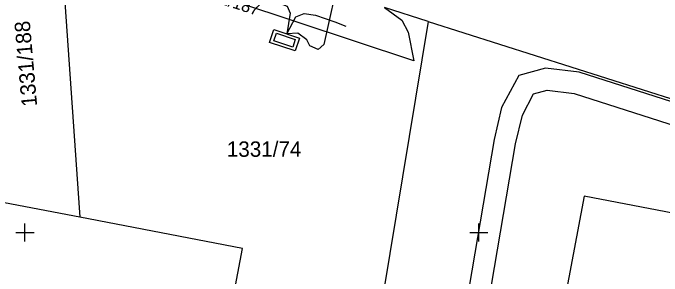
# Model space of a CAD drawing. Extents: x -601602 to -600882, y -1162594 to -1161950.
# Drawn here: x -601150.66 to -601114.91, y -1162127.4 to -1162112.9 of the extents above; entities that cross this region are included whole.
import ezdxf

# ---------------------------------------------------------------- set-up
doc = ezdxf.new("R2010")
doc.units = 0
for name, color, linetype in [('IS_EON_NN', 7, 'Continuous'), ('KN_Hranice parcel', 7, 'Continuous'), ('KN_Parcelní čísla', 7, 'Continuous'), ('KN_Věcná břemena k části', 7, 'Continuous'), ('X_SOUR_KRIZKY_SEVER', 7, 'Continuous')]:
    doc.layers.add(name, color=color, linetype=linetype)

# ---------------------------------------------------------------- blocks, each defined once
blk = doc.blocks.new('132_9')
at = {"layer": 'IS_EON_NN'}
for points in [[(-1.5, 1.5), (1.5, 1.5), (1.5, 0), (-1.5, 0)], [(-1.1, 1.2), (1.1, 1.2), (1.1, 0.3), (-1.1, 0.3)]]:
    blk.add_lwpolyline(points, close=True, dxfattribs=at)

msp = doc.modelspace()

# ---------------------------------------------------------------- linework, layer by layer
at = {"layer": 'IS_EON_NN'}
for points in [[(-601130.83, -1162102.5), (-601133.53, -1162114.65), (-601133.84, -1162114.91), (-601134.3, -1162114.72), (-601134.48, -1162114.39), (-601134.96, -1162114.02), (-601135.58, -1162114.05)], [(-601138.29, -1162111.45), (-601135.56, -1162112.52), (-601135.39, -1162112.91), (-601135.58, -1162114.05)], [(-601135.58, -1162114.05), (-601135.07, -1162113.12), (-601134.61, -1162112.94), (-601134, -1162113.02), (-601132.93, -1162113.4), (-601132.32, -1162113.64)]]:
    msp.add_lwpolyline(points, dxfattribs=at)
at = {"layer": 'KN_Hranice parcel'}
for p, q in [((-601148.03, -1162109.07), (-601146.98, -1162124.15)), ((-601127.79, -1162113.37), (-601130.19, -1162112.6)), ((-601127.79, -1162113.37), (-601132.96, -1162144.65)), ((-601127.79, -1162113.37), (-601109.09, -1162119.33)), ((-601146.98, -1162124.15), (-601153.26, -1162122.95))]:
    msp.add_line(p, q, dxfattribs=at)
for points in [[(-601130.19, -1162112.6), (-601129.24, -1162113.3), (-601128.89, -1162113.97), (-601128.58, -1162115.55), (-601148.03, -1162109.07)], [(-601091.03, -1162134.77), (-601093.93, -1162134.22), (-601092.77, -1162128.06), (-601119.19, -1162123), (-601124.02, -1162148.61), (-601098.1, -1162153.53), (-601099.02, -1162158.39)], [(-601145.82, -1162139.06), (-601137.26, -1162140.71), (-601135.56, -1162132.45), (-601139.12, -1162131.71), (-601138.01, -1162125.88), (-601146.98, -1162124.15)]]:
    msp.add_lwpolyline(points, dxfattribs=at)
at = {"layer": 'KN_Věcná břemena k části'}
msp.add_lwpolyline([(-601071.86, -1162133.64), (-601078.97, -1162129.14), (-601092.68, -1162124.75), (-601119.48, -1162116.16), (-601121.32, -1162115.94), (-601122.8, -1162116.34), (-601123.74, -1162118.12), (-601124.16, -1162119.88), (-601128.74, -1162146.87), (-601133.21, -1162146.17), (-601133.4, -1162147.34), (-601127.76, -1162148.23), (-601122.98, -1162120.12), (-601122.6, -1162118.54), (-601121.98, -1162117.36), (-601121.24, -1162117.16), (-601119.74, -1162117.34), (-601092.46, -1162126.08), (-601079.49, -1162130.24), (-601072.6, -1162134.6)], dxfattribs=at)
at = {"layer": 'X_SOUR_KRIZKY_SEVER'}
for p, q in [((-601150, -1162125.5), (-601150, -1162124.5)), ((-601125, -1162125.5), (-601125, -1162124.5)), ((-601150.5, -1162125), (-601149.5, -1162125)), ((-601125.5, -1162125), (-601124.5, -1162125))]:
    msp.add_line(p, q, dxfattribs=at)

# ---------------------------------------------------------------- block references
at = {"layer": 'IS_EON_NN', "xscale": 0.49999999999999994, "yscale": 0.5000000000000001, "rotation": 161.55303192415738}
msp.add_blockref('132_9', (-601135.58, -1162114.05), dxfattribs=at)

# ---------------------------------------------------------------- texts
at = {"layer": 'KN_Parcelní čísla'}
for s, height, rotation, p in [('1331/187', 0.6665, 342, (-601140.735, -1162111.917)), ('1331/188', 0.85, 95, (-601149.324, -1162118.029))]:
    msp.add_text(s, height=height, rotation=rotation, dxfattribs=at).set_placement(p)
msp.add_text('1331/74', height=0.85, dxfattribs=at).set_placement((-601138.879, -1162120.83))

doc.saveas('drawing.dxf')
